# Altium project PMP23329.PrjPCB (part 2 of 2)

## Sheet MCU and Communication.SchDoc
size A3; Date: Not shown in title block; ApprovedBy: Not shown in title block; CheckedBy: Not shown in title block; Author: Not shown in title block; CompanyName: Not shown in title block; Engineer: Not shown in title block; Organization: Not shown in title block; Address1: Not shown in title block; Address2: Not shown in title block; Address3: Not shown in title block; Address4: Not shown in title block; DocumentNumber: 1; Revision: Use project parameter SCH_Rev; SheetNumber: 4; SheetTotal: 7; PageSetup: Record=PageOptions¦CenterHorizontal=True¦CenterVertical=True¦PrintScale=1.00¦XCorrection=1.00¦YCorrection=1.00¦PrintKind=0¦BorderSize=5000000¦LeftOffset=0¦BottomOffset=0¦Orientation=2¦PaperLength=1000¦PaperWidth=1000¦Scale=100¦PaperSource=15¦PrintQuality=600¦MediaType=1¦DitherType=10¦PaperKind=Letter¦PrintScaleMode=1
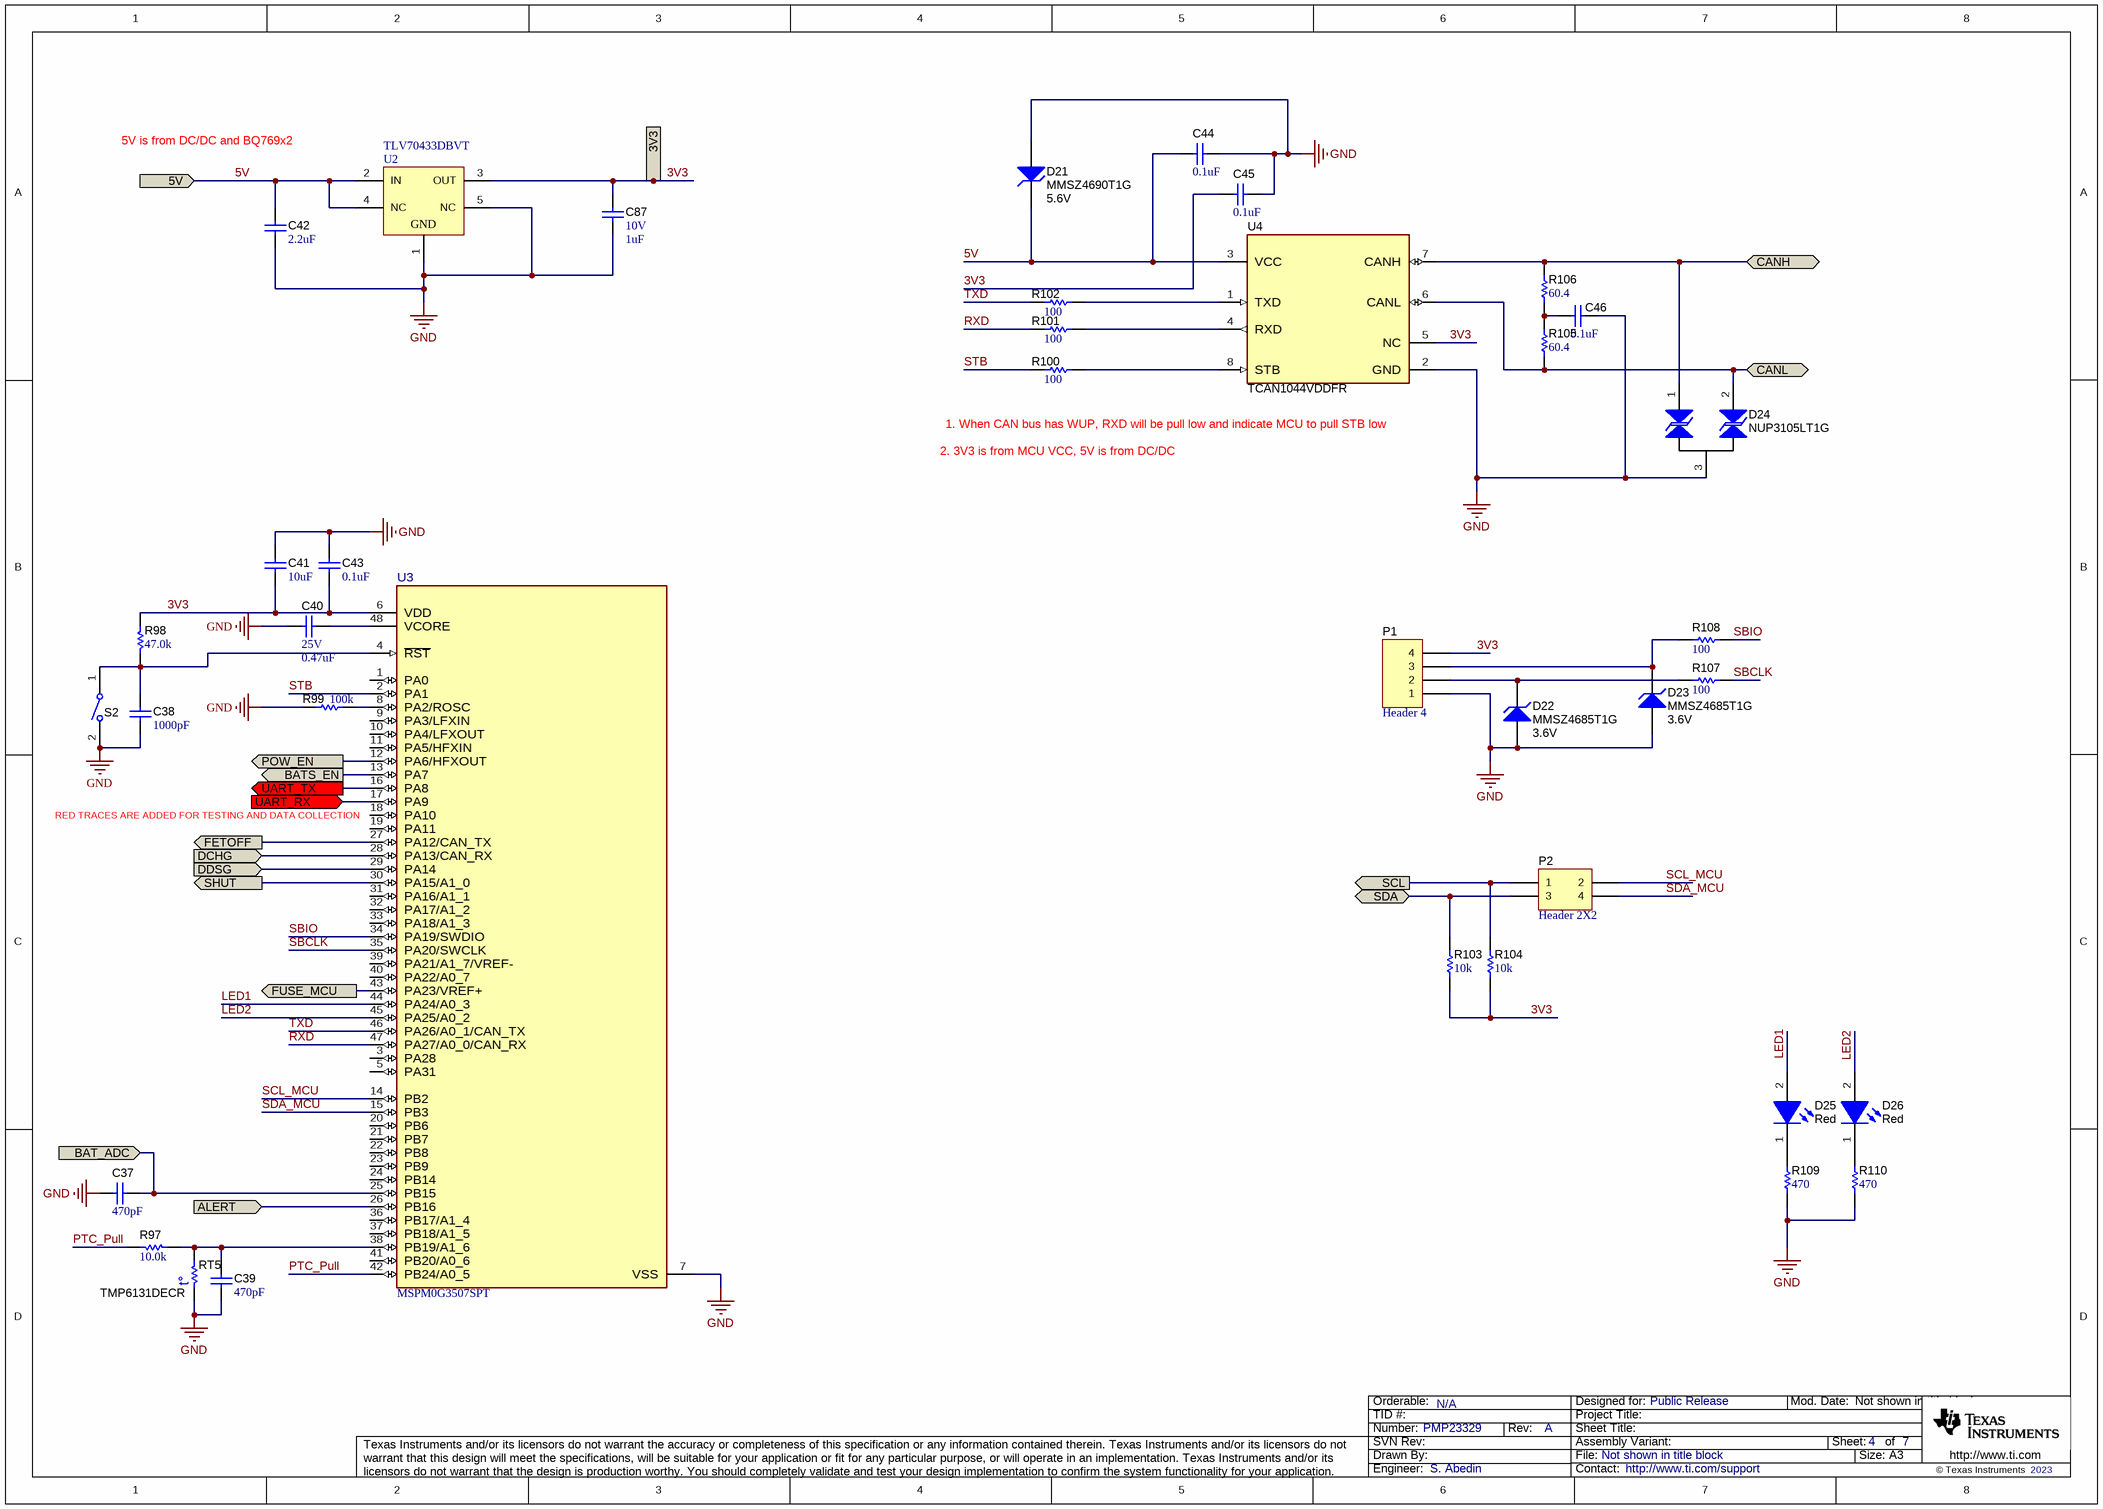
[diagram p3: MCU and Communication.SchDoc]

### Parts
C37  ValueDisplayed: 470pF  [0603S]  (hidden comment: GRM188R71H471KA01D)
C38  ValueDisplayed: 1000pF  [0603S]  (hidden comment: GRM1885C1H102JA01D)
C39  ValueDisplayed: 470pF  [0603S]  (hidden comment: GRM188R71H471KA01D)
C40  VDC_V: 25V  ValueDisplayed: 0.47uF  [1206L]  (hidden comment: 12063C474KAT2A)
C41  ValueDisplayed: 10uF  [0805_HV]  (hidden comment: CL21B106KOQNNNE)
C42  ValueDisplayed: 2.2uF  [0603S]  (hidden comment: EMK107BB7225MA-T)
C43  ValueDisplayed: 0.1uF  [0603S]  (hidden comment: GRM188R71H104KA93D)
C44  ValueDisplayed: 0.1uF  [0603S]  (hidden comment: GRM188R71H104KA93D)
C45  ValueDisplayed: 0.1uF  [0603S]  (hidden comment: GRM188R71H104KA93D)
C46  ValueDisplayed: 0.1uF  [0603S]  (hidden comment: GRM188R71H104KA93D)
C87  VDC_V: 10V  ValueDisplayed: 1uF  [0402S]  (hidden comment: GRM155R61A105KE15D)
D21  MMSZ4690T1G  value 5.6V  [SOD-123]
D22  MMSZ4685T1G  value 3.6V  [SOD-123]
D23  MMSZ4685T1G  value 3.6V  [SOD-123]
D24  NUP3105LT1G  [SOT-23]
D25  value Red  [WL-SMCW_RED]  (hidden comment: 150060RS75000)
D26  value Red  [WL-SMCW_RED]  (hidden comment: 150060RS75000)
P1  Header 4  [HDR1X4]
P2  Header 2X2  [HDR2X2]
R97  ValueDisplayed: 10.0k  [0603S]  (hidden comment: CRCW060310K0FKEA)
R98  ValueDisplayed: 47.0k  [0603S]  (hidden comment: RC0603FR-0747KL)
R99  ValueDisplayed: 100k  [0603S]  (hidden comment: RT0603BRD07100KL)
R100  ValueDisplayed: 100  [0603S]  (hidden comment: CRCW0603100RFKEA)
R101  ValueDisplayed: 100  [0603S]  (hidden comment: CRCW0603100RFKEA)
R102  ValueDisplayed: 100  [0603S]  (hidden comment: CRCW0603100RFKEA)
R103  ValueDisplayed: 10k  [0603S]  (hidden comment: CRCW060310K0JNEA)
R104  ValueDisplayed: 10k  [0603S]  (hidden comment: CRCW060310K0JNEA)
R105  ValueDisplayed: 60.4  [0603S]  (hidden comment: RC0603FR-0760R4L)
R106  ValueDisplayed: 60.4  [0603S]  (hidden comment: RC0603FR-0760R4L)
R107  ValueDisplayed: 100  [0603S]  (hidden comment: CRCW0603100RFKEA)
R108  ValueDisplayed: 100  [0603S]  (hidden comment: CRCW0603100RFKEA)
R109  ValueDisplayed: 470  [0603S]  (hidden comment: RC0603FR-07470RL)
R110  ValueDisplayed: 470  [0603S]  (hidden comment: RC0603FR-07470RL)
RT5  TMP6131DECR  [DEC0002A]
S2  RS-032G05A3-SM RT  [SW_RS-032G05A3-SM]  (value not drawn)
U2  TLV70433DBVT  [DBV0005A_N]
U3  MSPM0G3507SPT  [PT0048A-MFG]
U4  PartNumber: TCAN1044VDDFR  [DDF0008A-MFG]  (hidden comment: TCAN1044DDFRQ1)

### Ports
3V3 (out), 5V (in), ALERT (in), BAT_ADC (in), BATS_EN (out), CANH (bidir), CANL (bidir), DCHG (in), DDSG (in), FETOFF (out), FUSE_MCU (out), POW_EN (out), SCL (out), SDA (bidir), SHUT (out), UART_RX (in), UART_TX (out)

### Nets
GND: C37.1 C38.2 C39.2 C40.2 C41.1 C42.2 C43.1 C44.2 C45.2 C46.1 C87.2 D21.2(A) D22.2(A) D23.2(A) D24.3 P1.1 R99.1 R109.1 R110.1 RT5.1 S2.2 U2.1(GND) U2.5(NC) U3.7(VSS) U4.2(GND)
3V3: C41.2 C43.2 C45.1 C87.1 P1.4 R98.2 R103.1 R104.1 U2.3(OUT) U3.6(VDD) U4.5(NC) ; port 3V3
5V: C42.1 C44.1 D21.1(K) U2.2(IN) U2.4(NC) U4.3(VCC) ; port 5V
ALERT: U3.26(PB16) ; port ALERT
BAT_ADC: C37.2 U3.25(PB15) ; port BAT_ADC
BATS_EN: U3.13(PA7) ; port BATS_EN
CANH: D24.1 R106.1 U4.7(CANH) ; port CANH
CANL: D24.2 R105.2 U4.6(CANL) ; port CANL
DCHG: U3.28(PA13/CAN_RX) ; port DCHG
DDSG: U3.29(PA14) ; port DDSG
FETOFF: U3.27(PA12/CAN_TX) ; port FETOFF
FUSE_MCU: U3.43(PA23/VREF+) ; port FUSE_MCU
LED1: D25.2(A) U3.44(PA24/A0_3)
LED2: D26.2(A) U3.45(PA25/A0_2)
POW_EN: U3.12(PA6/HFXOUT) ; port POW_EN
PTC_Pull: R97.2 U3.42(PB24/A0_5)
RXD: R101.2 U3.47(PA27/A0_0/CAN_RX)
SBCLK: R107.1 U3.35(PA20/SWCLK)
SBIO: R108.1 U3.34(PA19/SWDIO)
SCL_MCU: P2.1 R104.2 ; port SCL
SCL_MCU: P2.2 U3.14(PB2)  [a separate net that carries the same name]
SDA_MCU: P2.3 R103.2 ; port SDA
SDA_MCU: P2.4 U3.15(PB3)  [a separate net that carries the same name]
SHUT: U3.30(PA15/A1_0) ; port SHUT
STB: R100.2 U3.2(PA1)
TXD: R102.2 U3.46(PA26/A0_1/CAN_TX)
UART_RX: U3.17(PA9) ; port UART_RX
UART_TX: U3.16(PA8) ; port UART_TX
NetC38_1: C38.1 R98.1 S2.1 U3.4(~{RST})
NetC39_1: C39.1 R97.1 RT5.2 U3.38(PB19/A1_6)
NetC40_1: C40.1 U3.48(VCORE)
NetC46_2: C46.2 R105.1 R106.2
NetD22_1: D22.1(K) P1.2 R107.2
NetD23_1: D23.1(K) P1.3 R108.2
NetD25_1: D25.1(K) R109.2
NetD26_1: D26.1(K) R110.2
NetR99_2: R99.2 U3.8(PA2/ROSC)
NetR100_1: R100.1 U4.8(STB)
NetR101_1: R101.1 U4.4(RXD)
NetR102_1: R102.1 U4.1(TXD)

Not connected (* = marked no-connect by the designer): U3 1(PA0) 3(PA28) 5(PA31) 9(PA3/LFXIN) 10(PA4/LFXOUT) 11(PA5/HFXIN) 18(PA10) 19(PA11) 20(PB6) 21(PB7) 22(PB8) 23(PB9) 24(PB14) 31(PA16/A1_1) 32(PA17/A1_2) 33(PA18/A1_3) 36(PB17/A1_4) 37(PB18/A1_5) 39(PA21/A1_7/VREF-) 40(PA22/A0_7) 41(PB20/A0_6)

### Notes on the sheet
- 5V is from DC/DC and BQ769x2
- 2. 3V3 is from MCU VCC, 5V is from DC/DC
- 1. When CAN bus has WUP, RXD will be pull low and indicate MCU to pull STB low
- RED TRACES ARE ADDED FOR TESTING AND DATA COLLECTION
- N/A

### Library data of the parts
C37 C39 = CMP-0007455-4: CAP, CERM, 470 pF, 50 V, +/- 10%, X7R, 0603; Manufacturer: MuRata; Polarized: N; Value: 470pF; U/M: EA; Value1: Unknown; VDC_V: 50V; TaMin_C: -55°C; TaMax_C: 125°C; Cap_Case: 0603; SizeArea_mm2: 1.28; SizeAreaWB_mm2: 4.68; SizeX_mm: 1.6; SizeY_mm: 0.8; SizeZ_mm: 1; AEC Category: Q200
C38 = CMP-0007173-4: CAP, CERM, 1000 pF, 50 V, +/- 5%, C0G/NP0, 0603; Manufacturer: MuRata; Polarized: N; Value: 1000pF; U/M: EA; Cap_F: 1nF; Value1: Unknown; VDC_V: 50V; TaMin_C: -55°C; TaMax_C: 125°C; Cap_Case: 0603; SizeArea_mm2: 1.28; SizeAreaWB_mm2: 4.68; SizeX_mm: 1.6; SizeY_mm: 0.8; SizeZ_mm: 1; AEC Category: Q200
C40 = CMP-0008510-2: CAP, CERM, 0.47 uF, 25 V, +/- 10%, X7R, 1206; Manufacturer: AVX; TaMin_C: -55°C; ESR_ohm: 18m; Polarized: N; SizeAreaWB_mm2: 10.92; Value1: 0.018 ohm; U/M: EA; Value: 0.47uF; TaMax_C: 125°C; SizeZ_mm: 1.35; SizeX_mm: 3.2; SizeY_mm: 1.6; Cap_Case: 1206; SizeArea_mm2: 5.12; Cap_F: 470nF; AEC Category: Q200
C41 = CMP-0007995-2: CAP, CERM, 10 uF, 16 V, +/- 10%, X7R, 0805; Manufacturer: Samsung Electro-Mechanics; Polarized: N; Value: 10uF; U/M: EA; Cap_F: 10µF; Value1: Unknown; VDC_V: 16V; TaMin_C: -55°C; TaMax_C: 125°C; Cap_Case: 0805; SizeArea_mm2: 2.5; SizeAreaWB_mm2: 6.75; SizeX_mm: 2; SizeY_mm: 1.25; SizeZ_mm: 1.45; AEC Category: Q200
C42 = CMP-0064934-4: CAP, CERM, 2.2 uF, 16 V,+/- 10%, X7R, 0603; Manufacturer: Taiyo Yuden; Polarized: N; Value: 2.2uF; U/M: EA; Cap_F: 2.2µF; Value1: Unknown; VDC_V: 16V; TaMin_C: -55°C; TaMax_C: 125°C; Cap_Case: 0603; SizeArea_mm2: 1.28; SizeAreaWB_mm2: 4.68; SizeX_mm: 1.6; SizeY_mm: 0.8; SizeZ_mm: 1; AEC Category: Q200
C43-C46 = CMP-0007434-4: CAP, CERM, 0.1 uF, 50 V, +/- 10%, X7R, 0603; Manufacturer: MuRata; Polarized: N; Value: 0.1uF; U/M: EA; Cap_F: 100nF; Value1: Unknown; VDC_V: 50V; TaMin_C: -55°C; TaMax_C: 125°C; Cap_Case: 0603; SizeArea_mm2: 1.28; SizeAreaWB_mm2: 4.68; SizeX_mm: 1.6; SizeY_mm: 0.8; SizeZ_mm: 1; AEC Category: Q200
C87 = CMP-0006563-2: CAP, CERM, 1 uF, 10 V, +/- 10%, X5R, 0402; Manufacturer: MuRata; TaMin_C: -55°C; Polarized: N; SizeAreaWB_mm2: 3; Value1: Unknown; U/M: EA; Value: 1uF; TaMax_C: 85°C; SizeZ_mm: 0.6; SizeX_mm: 1; SizeY_mm: 0.5; Cap_Case: 0402; Cap_F: 1µF; AEC Category: Q200
D21 = CMP-0005787-3: Diode, Zener, 5.6 V, 500 mW, SOD-123; Manufacturer: ON Semiconductor; Power_W: 500mW; Value1: 0.5W; RJA_CperW: 340; SizeAreaWB_mm2: 13.095; SizeArea_mm2: 6.545; SizeX_mm: 3.85; SizeY_mm: 1.7; SizeZ_mm: 1.35; AEC Category: Q101
D22 D23 = CMP-0005782-3: Diode, Zener, 3.6 V, 500 mW, SOD-123; Manufacturer: ON Semiconductor; Power_W: 500mW; Value1: 0.5W; RJA_CperW: 340; SizeAreaWB_mm2: 13.095; SizeArea_mm2: 6.545; SizeX_mm: 3.85; SizeY_mm: 1.7; SizeZ_mm: 1.35; AEC Category: Q101
D24 = CMP-0078391-3: Diode, TVS, Bi, 32 V, 66 Vc, AEC-Q101, SOT-23; Manufacturer: ON Semiconductor; Value: 32V; Value1: 350W; SizeAreaWB_mm2: 14; SizeArea_mm2: 7.5; SizeX_mm: 2.5; SizeY_mm: 3; SizeZ_mm: 1.1; AEC Category: Q101; AEC Qualified: Y; Ipp: 8A; Vbr_Min: 35.6V; Vc: 66V
D25 D26 = CMP-0002947-3: LED, Red, SMD; Manufacturer: Wurth Elektronik; Type: AlInGaP; Vf_V: 2V; Io_A: 30mA; Vr_V: 5V; Tjmax_C: 85°C; Power_TotalModule: 72mW; Value1: 0.072W; Angle: 140
P1 = Header 4: Header, 4-Pin
P2 = Header 2X2: Header, 2-Pin, Dual row
R97 = CMP-0021998-4: RES, 10.0 k, 1%, 0.1 W, AEC-Q200 Grade 0, 0603; Manufacturer: Vishay-Dale; Value: 10.0k; Res_ohm: 10k; Value_Code: 10k0; Power_W: 100mW; Value2: 0.1W; VDC_V: 75V; TempCo: 100 ppm/C; SizeArea_mm2: 1.28; SizeX_mm: 1.6; SizeY_mm: 0.8; SizeZ_mm: 1; EIA_Code: E96; AEC Category: Q200; AEC Qualified: Y; AEC Grade: 0
R98 = CMP-0023133-5: RES, 47.0 k, 1%, 0.1 W, 0603; Manufacturer: Yageo; Value: 47.0k; Res_ohm: 47k; Value_Code: 47k0; Power_W: 100mW; Value2: 0.1W; VDC_V: 75V; TempCo: 100 ppm/C; SizeArea_mm2: 1.28; SizeX_mm: 1.6; SizeY_mm: 0.8; SizeZ_mm: 1; AEC Category: Q200; AEC Qualified: N; SizeAreaWB_mm2: 4.68
R99 = CMP-0023630-3: RES, 100 k, 0.1%, 0.1 W, 0603; Manufacturer: Yageo America; Value: 100k; Power_W: 100mW; Value2: 0.1W; VDC_V: 75V; TempCo: 25 ppm/C; SizeArea_mm2: 1.28; SizeX_mm: 1.6; SizeY_mm: 0.8; SizeZ_mm: 1; EIA_Code: E192; U/M: EA; AEC Category: Q200
R100-R102 R107 R108 = CMP-0021991-4: RES, 100, 1%, 0.1 W, AEC-Q200 Grade 0, 0603; Manufacturer: Vishay-Dale; Value: 100; Value_Code: 100R; Power_W: 100mW; Value2: 0.1W; VDC_V: 75V; TempCo: 100 ppm/C; SizeArea_mm2: 1.28; SizeX_mm: 1.6; SizeY_mm: 0.8; SizeZ_mm: 1; EIA_Code: E96; AEC Category: Q200; AEC Qualified: Y; AEC Grade: 0
R103 R104 = CMP-0025701-4: RES, 10 k, 5%, 0.1 W, AEC-Q200 Grade 0, 0603; Manufacturer: Vishay-Dale; Value: 10k; Value_Code: 10k0; Power_W: 100mW; Value2: 0.1W; VDC_V: 75V; TempCo: 200 ppm/C; SizeArea_mm2: 1.28; SizeX_mm: 1.6; SizeY_mm: 0.8; SizeZ_mm: 1; EIA_Code: E24; AEC Category: Q200; AEC Qualified: Y; AEC Grade: 0
R105 R106 = CMP-0023213-5: RES, 60.4, 1%, 0.1 W, 0603; Manufacturer: Yageo; Value: 60.4; Value_Code: 60R4; Power_W: 100mW; Value2: 0.1W; VDC_V: 75V; TempCo: 100 ppm/C; SizeArea_mm2: 1.28; SizeX_mm: 1.6; SizeY_mm: 0.8; SizeZ_mm: 1; EIA_Code: E96; AEC Category: Q200; AEC Qualified: N; SizeAreaWB_mm2: 4.68
R109 R110 = CMP-0023129-5: RES, 470, 1%, 0.1 W, 0603; Manufacturer: Yageo; Value: 470; Value_Code: 470R; Power_W: 100mW; Value2: 0.1W; VDC_V: 75V; TempCo: 100 ppm/C; SizeArea_mm2: 1.28; SizeX_mm: 1.6; SizeY_mm: 0.8; SizeZ_mm: 1; AEC Category: Q200; AEC Qualified: N; SizeAreaWB_mm2: 4.68
RT5 = CMP-0084566-1: Thermistor, DEC0002A (X1SON-2); Alternate Manufacturer: Texas Instruments; Alternate PartNumber: TMP6131DECT; CompType: IC; AEC Category: Q200; SizeX_mm: 1; AEC Qualified: N; SizeZ_mm: 0.5; SizeArea_mm2: 0.6; SizeAreaWB_mm2: 3.2
S2 = CMP-0002210-1: Switch, Tactile, SPST-NO, 0.05A, 12V, SMD; Manufacturer: C&K Components; SwitchFunction: Off-Mom; PositionCount: 1; CurrentRating_mA: 50A
U2 = CMP-0035592-1: Single Output LDO, 150 mA, Fixed 3.3 V Output, 2.5 to 24 V Input, with Ultra-Low IQ, 5-pin SOT-23 (DBV), -40 to 125 degC, Green (RoHS & no Sb/Br); Manufacturer: Texas Instruments; Accuracy(%): 2; Fixed Output Options(V): 3.3; Iout(Max)(A): 0.15; Iq(Typ)(mA): 0.003; SubFamily: Single Channel LDO; Vdo(Typ)(mV): 400; Vin(Max)(V): 24; Vin(Min)(V): 2.5
U3 = CMP-0093961-1: Mixed-Signal Microcontrollers with CAN-FD Interface ARM Cortex-M0+ 32bits 128KB Flash 32KB RAM LQFP48 AEC Q-200 Grade 1 80MHz; Manufacturer: Texas Instruments; Number Of I/Os: 44; Interface: I2C,SPI,UART,CAN,LIN,IrDA,SMBus; Number Of I2C Channels: 2; AEC Grade: Grade 1; TaMin_C: -40°C; Number Of Adc Channels: 15; Standoff Height: 0.05mm; Ram Size: 32KBytes; Number Of Pwm Channels: 20; Min Supply Voltage: 1.62V; AEC Qualified: Yes; Number Of Timers/Counters: 6; SizeZ_mm: 1.6mm; Number Of Cores: 1; TaMax_C: +125°C; TJmax_C: +130°C; Memory Size: 128KBytes; Max Supply Voltage: 3.6V; Number Of Uart Channels: 4
U4 = CMP-0089901-1: Automotive High Speed CAN Transceiver; Manufacturer: Texas Instruments; Min Supply Voltage: 4.5V; TaMin_C: -40°C; AEC Grade: Grade 1; Standoff Height: 0mm; SizeZ_mm: 1.1mm; TaMax_C: +125°C; Max Supply Voltage: 5.5V; Nominal Supply Current: 5-180mA; TJmax_C: +150°C; AEC Qualified: Yes

## Sheet High-side MOSFETs and driver.SchDoc
size A3; Date: Not shown in title block; ApprovedBy: Not shown in title block; CheckedBy: Not shown in title block; Author: Not shown in title block; CompanyName: Not shown in title block; Engineer: Not shown in title block; Organization: Not shown in title block; Address1: Not shown in title block; Address2: Not shown in title block; Address3: Not shown in title block; Address4: Not shown in title block; DocumentNumber: 1; Revision: Use project parameter SCH_Rev; SheetNumber: 6; SheetTotal: 7; PageSetup: Record=PageOptions¦CenterHorizontal=True¦CenterVertical=True¦PrintScale=1.00¦XCorrection=1.00¦YCorrection=1.00¦PrintKind=0¦BorderSize=5000000¦LeftOffset=0¦BottomOffset=0¦Orientation=2¦PaperLength=1000¦PaperWidth=1000¦Scale=100¦PaperSource=15¦PrintQuality=600¦MediaType=1¦DitherType=10¦PaperKind=Letter¦PrintScaleMode=1
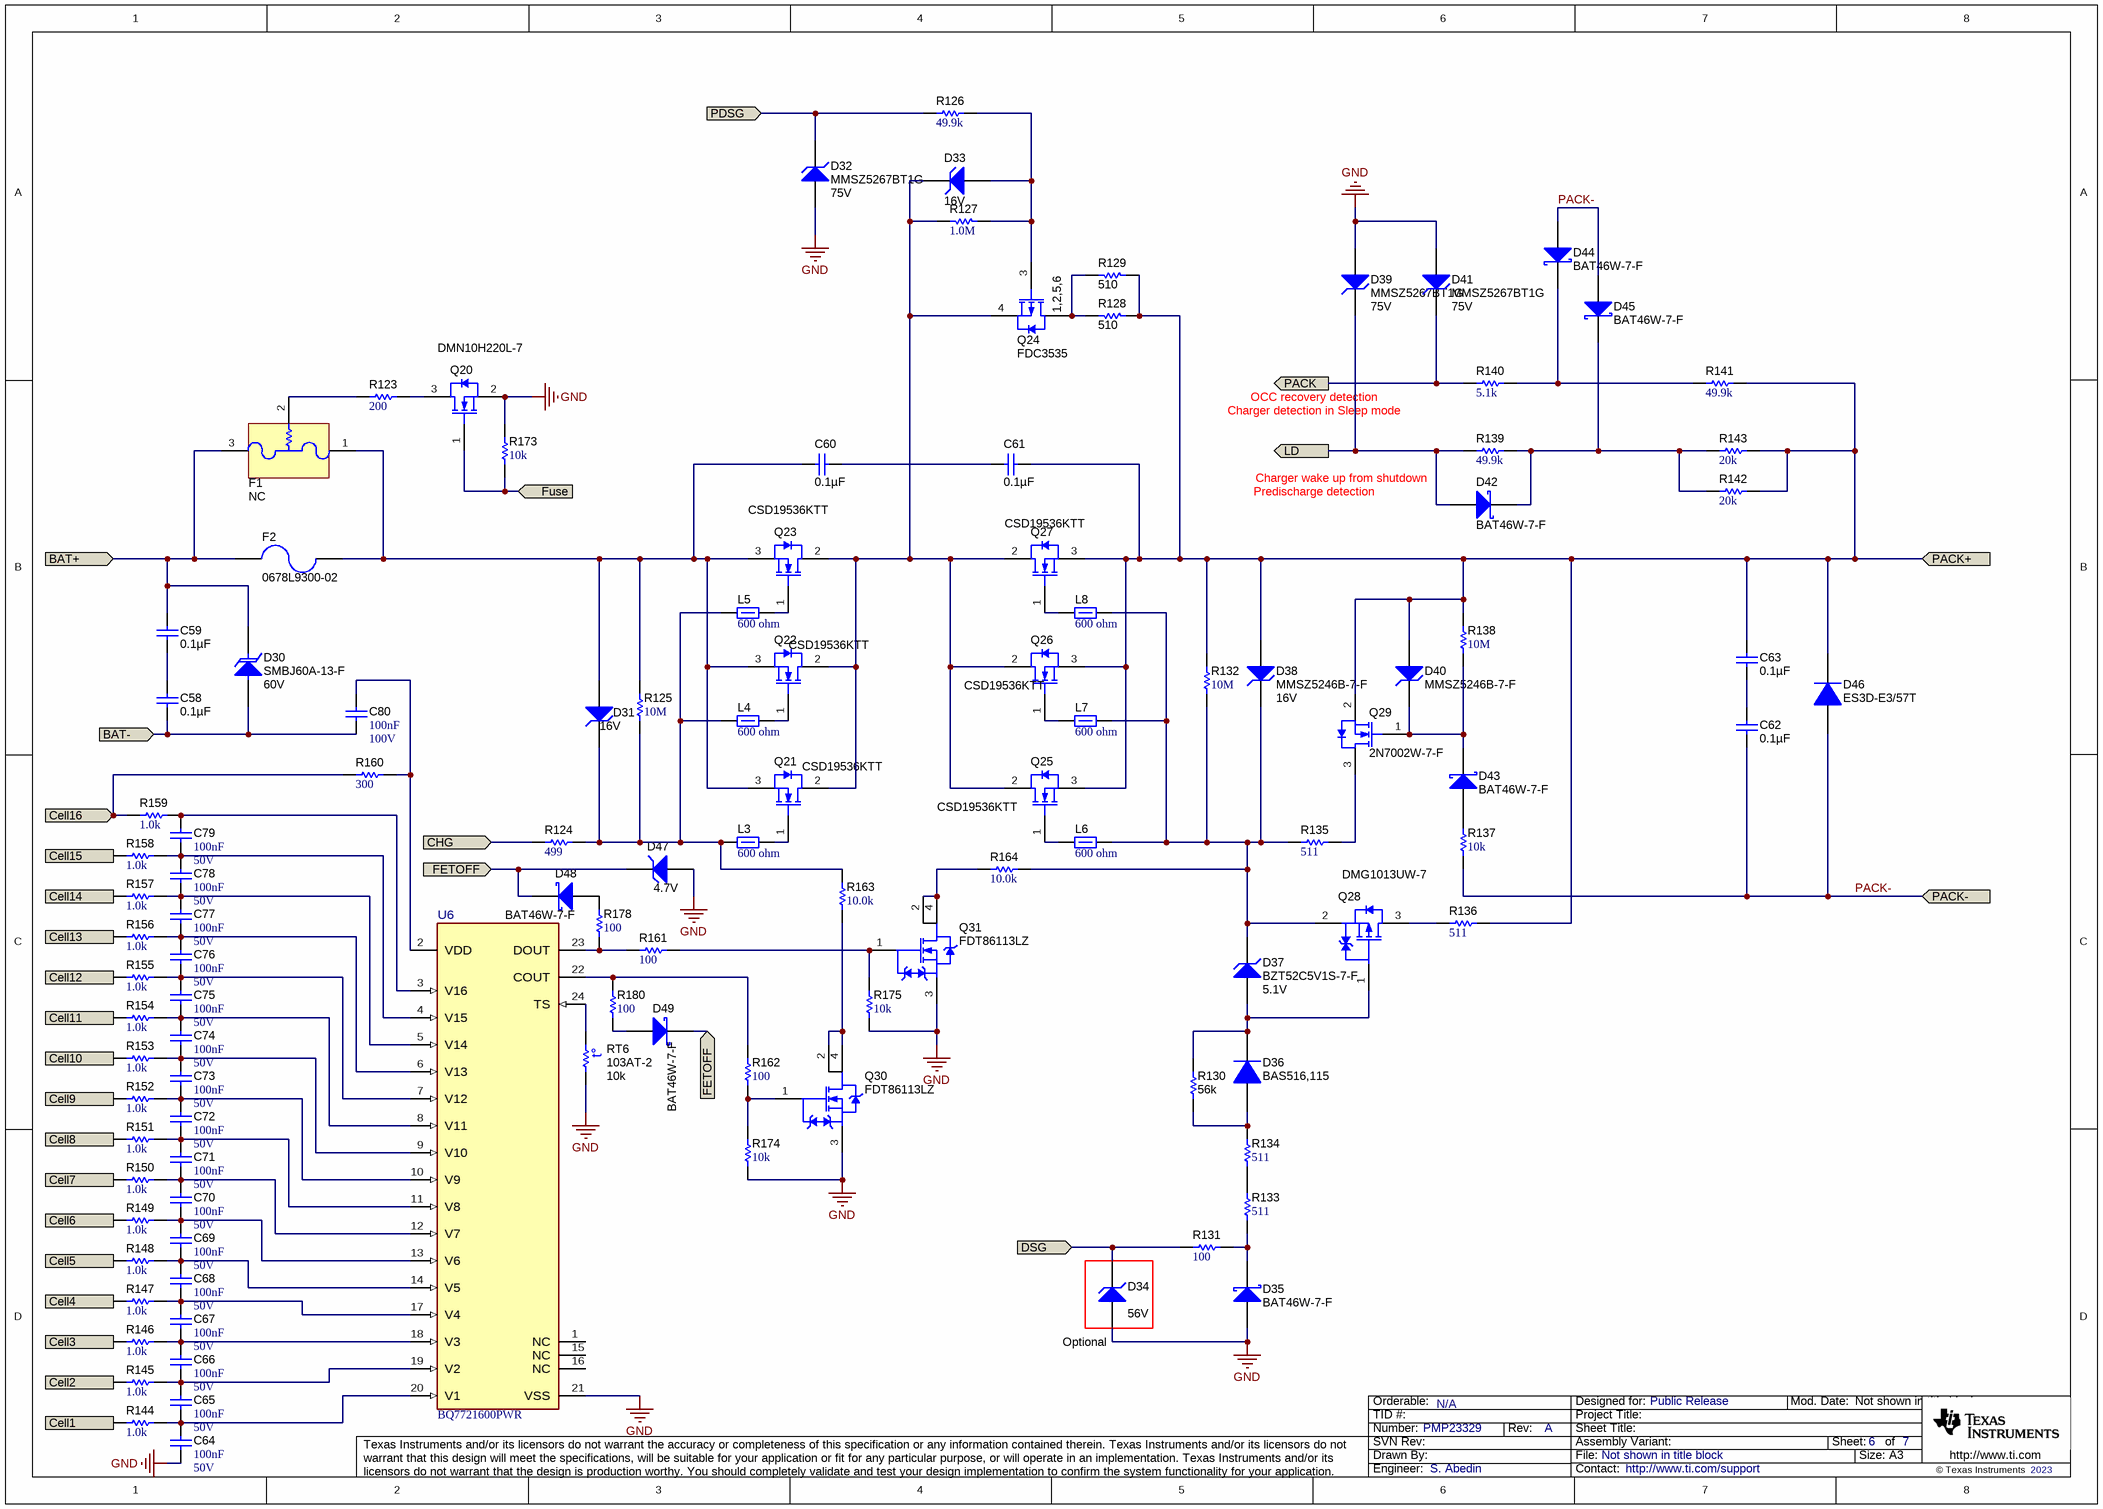
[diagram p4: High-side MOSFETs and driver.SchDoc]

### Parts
C58  ValueDisplayed: 0.1µF  [0603S]  (hidden comment: GRM188R72A104KA35D)
C59  ValueDisplayed: 0.1µF  [0603S]  (hidden comment: GRM188R72A104KA35D)
C60  ValueDisplayed: 0.1µF  [0603S]  (hidden comment: GRM188R72A104KA35D)
C61  ValueDisplayed: 0.1µF  [0603S]  (hidden comment: GRM188R72A104KA35D)
C62  ValueDisplayed: 0.1µF  [0603S]  (hidden comment: GRM188R72A104KA35D)
C63  ValueDisplayed: 0.1µF  [0603S]  (hidden comment: GRM188R72A104KA35D)
C64  Cap_F: 100nF  VDC_V: 50V  [0603S]  (hidden comment: 885012206095)
C65  Cap_F: 100nF  VDC_V: 50V  [0603S]  (hidden comment: 885012206095)
C66  Cap_F: 100nF  VDC_V: 50V  [0603S]  (hidden comment: 885012206095)
C67  Cap_F: 100nF  VDC_V: 50V  [0603S]  (hidden comment: 885012206095)
C68  Cap_F: 100nF  VDC_V: 50V  [0603S]  (hidden comment: 885012206095)
C69  Cap_F: 100nF  VDC_V: 50V  [0603S]  (hidden comment: 885012206095)
C70  Cap_F: 100nF  VDC_V: 50V  [0603S]  (hidden comment: 885012206095)
C71  Cap_F: 100nF  VDC_V: 50V  [0603S]  (hidden comment: 885012206095)
C72  Cap_F: 100nF  VDC_V: 50V  [0603S]  (hidden comment: 885012206095)
C73  Cap_F: 100nF  VDC_V: 50V  [0603S]  (hidden comment: 885012206095)
C74  Cap_F: 100nF  VDC_V: 50V  [0603S]  (hidden comment: 885012206095)
C75  Cap_F: 100nF  VDC_V: 50V  [0603S]  (hidden comment: 885012206095)
C76  Cap_F: 100nF  VDC_V: 50V  [0603S]  (hidden comment: 885012206095)
C77  Cap_F: 100nF  VDC_V: 50V  [0603S]  (hidden comment: 885012206095)
C78  Cap_F: 100nF  VDC_V: 50V  [0603S]  (hidden comment: 885012206095)
C79  Cap_F: 100nF  VDC_V: 50V  [0603S]  (hidden comment: 885012206095)
C80  Cap_F: 100nF  VDC_V: 100V  [0603S]  (hidden comment: GCJ188R72A104KA01D)
D30  SMBJ60A-13-F  value 60V  [SMB]
D31  value 16V  [SOD-123]  (hidden comment: MMSZ5246B-7-F)
D32  MMSZ5267BT1G  value 75V  [SOD-123]
D33  value 16V  [SOD-123]  (hidden comment: MMSZ5246B-7-F)
D34  value 56V  [SOD-123]  (hidden comment: MMSZ5263BT1G)
D35  BAT46W-7-F  [SOD-123]
D36  BAS516,115  [SOD-523]
D37  BZT52C5V1S-7-F  value 5.1V  [SOD-323]
D38  MMSZ5246B-7-F  value 16V  [SOD-123]
D39  MMSZ5267BT1G  value 75V  [SOD-123]
D40  MMSZ5246B-7-F  [SOD-123]
D41  MMSZ5267BT1G  value 75V  [SOD-123]
D42  BAT46W-7-F  [SOD-123]
D43  BAT46W-7-F  [SOD-123]
D44  BAT46W-7-F  [SOD-123]
D45  BAT46W-7-F  [SOD-123]
D46  ES3D-E3/57T  [SMC]
D47  value 4.7V  [SOD-323]  (hidden comment: CMDZ4L7 TR)
D48  BAT46W-7-F  [SOD-123]
D49  BAT46W-7-F  [SOD-123]
F1  NC  [FUSE_SFK-xx30x]
F2  0678L9300-02  [Fuse_0678L]
L3  ValueDisplayed: 600 ohm  [0603S]  (hidden comment: 74279265)
L4  ValueDisplayed: 600 ohm  [0603S]  (hidden comment: 74279265)
L5  ValueDisplayed: 600 ohm  [0603S]  (hidden comment: 74279265)
L6  ValueDisplayed: 600 ohm  [0603S]  (hidden comment: 74279265)
L7  ValueDisplayed: 600 ohm  [0603S]  (hidden comment: 74279265)
L8  ValueDisplayed: 600 ohm  [0603S]  (hidden comment: 74279265)
Q20  DMN10H220L-7  [SOT-23]
Q21  CSD19536KTT  [KTT0002A]
Q22  CSD19536KTT  [KTT0002A]
Q23  CSD19536KTT  [KTT0002A]
Q24  FDC3535  [SSOT-6]
Q25  CSD19536KTT  [KTT0002A]
Q26  CSD19536KTT  [KTT0002A]
Q27  CSD19536KTT  [KTT0002A]
Q28  DMG1013UW-7  [SOT-323]
Q29  2N7002W-7-F  [SOT-323]
Q30  FDT86113LZ  [SOT-223]
Q31  FDT86113LZ  [SOT-223]
R123  ValueDisplayed: 200  [0603S]  (hidden comment: CRCW0603200RFKEA)
R124  ValueDisplayed: 499  [1206L]  (hidden comment: ERJ-8ENF4990V)
R125  ValueDisplayed: 10M  [0603S]  (hidden comment: CRCW060310M0JNEA)
R126  ValueDisplayed: 49.9k  [0603S]  (hidden comment: RT0603BRD0749K9L)
R127  ValueDisplayed: 1.0M  [0603S]  (hidden comment: CRCW06031M00JNEA)
R128  ValueDisplayed: 510  [2512]  (hidden comment: RC2512JK-07510RL)
R129  ValueDisplayed: 510  [2512]  (hidden comment: RC2512JK-07510RL)
R130  ValueDisplayed: 56k  [0805_HV]  (hidden comment: RC0805JR-0756KL)
R131  ValueDisplayed: 100  [0603S]  (hidden comment: CRCW0603100RFKEA)
R132  ValueDisplayed: 10M  [0603S]  (hidden comment: CRCW060310M0JNEA)
R133  ValueDisplayed: 511  [0805_HV1]  (hidden comment: CRCW0805511RFKEA)
R134  ValueDisplayed: 511  [0805_HV]  (hidden comment: CRCW0805511RFKEA)
R135  ValueDisplayed: 511  [0805_HV]  (hidden comment: CRCW0805511RFKEA)
R136  ValueDisplayed: 511  [0603S]  (hidden comment: CRCW0603511RFKEA)
R137  ValueDisplayed: 10k  [0603S]  (hidden comment: CRCW060310K0JNEA)
R138  ValueDisplayed: 10M  [0603S]  (hidden comment: CRCW060310M0JNEA)
R139  ValueDisplayed: 49.9k  [0603S]  (hidden comment: RT0603BRD0749K9L)
R140  ValueDisplayed: 5.1k  [0603S]  (hidden comment: CRCW06035K10JNEA)
R141  ValueDisplayed: 49.9k  [0603S]  (hidden comment: RT0603BRD0749K9L)
R142  ValueDisplayed: 20k  [0603S]  (hidden comment: CRCW060320K0JNEA)
R143  ValueDisplayed: 20k  [0603S]  (hidden comment: CRCW060320K0JNEA)
R144  ValueDisplayed: 1.0k  [0402S]  (hidden comment: ERJ-2GEJ102X)
R145  ValueDisplayed: 1.0k  [0402S]  (hidden comment: ERJ-2GEJ102X)
R146  ValueDisplayed: 1.0k  [0402S]  (hidden comment: ERJ-2GEJ102X)
R147  ValueDisplayed: 1.0k  [0402S]  (hidden comment: ERJ-2GEJ102X)
R148  ValueDisplayed: 1.0k  [0402S]  (hidden comment: ERJ-2GEJ102X)
R149  ValueDisplayed: 1.0k  [0402S]  (hidden comment: ERJ-2GEJ102X)
R150  ValueDisplayed: 1.0k  [0402S]  (hidden comment: ERJ-2GEJ102X)
R151  ValueDisplayed: 1.0k  [0402S]  (hidden comment: ERJ-2GEJ102X)
R152  ValueDisplayed: 1.0k  [0402S]  (hidden comment: ERJ-2GEJ102X)
R153  ValueDisplayed: 1.0k  [0402S]  (hidden comment: ERJ-2GEJ102X)
R154  ValueDisplayed: 1.0k  [0402S]  (hidden comment: ERJ-2GEJ102X)
R155  ValueDisplayed: 1.0k  [0402S]  (hidden comment: ERJ-2GEJ102X)
R156  ValueDisplayed: 1.0k  [0402S]  (hidden comment: ERJ-2GEJ102X)
R157  ValueDisplayed: 1.0k  [0402S]  (hidden comment: ERJ-2GEJ102X)
R158  ValueDisplayed: 1.0k  [0402S]  (hidden comment: ERJ-2GEJ102X)
R159  ValueDisplayed: 1.0k  [0402S]  (hidden comment: ERJ-2GEJ102X)
R160  ValueDisplayed: 300  [0603S]  (hidden comment: CRCW0603300RJNEA)
R161  ValueDisplayed: 100  [0603S]  (hidden comment: CRCW0603100RJNEA)
R162  ValueDisplayed: 100  [0603S]  (hidden comment: CRCW0603100RJNEA)
R163  ValueDisplayed: 10.0k  [1206]  (hidden comment: CRCW120610K0FKEAHP)
R164  ValueDisplayed: 10.0k  [1206]  (hidden comment: CRCW120610K0FKEAHP)
R173  ValueDisplayed: 10k  [0603S]  (hidden comment: CRCW060310K0JNEA)
R174  ValueDisplayed: 10k  [0603S]  (hidden comment: CRCW060310K0JNEA)
R175  ValueDisplayed: 10k  [0603S]  (hidden comment: CRCW060310K0JNEA)
R178  ValueDisplayed: 100  [0603S]  (hidden comment: CRCW0603100RJNEA)
R180  ValueDisplayed: 100  [0603S]  (hidden comment: CRCW0603100RJNEA)
RT6  103AT-2  value 10k  [THERMISTOR_103AT-2]
U6  BQ7721600PWR  [PW0024A-MFG]

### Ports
BAT+ (in), BAT- (in), Cell1 (in), Cell2 (in), Cell3 (in), Cell4 (in), Cell5 (in), Cell6 (in), Cell7 (in), Cell8 (in), Cell9 (in), Cell10 (in), Cell11 (in), Cell12 (in), Cell13 (in), Cell14 (in), Cell15 (in), Cell16 (in), CHG (in), DSG (in), FETOFF (in), Fuse (in), LD (out), PACK (out), PACK+ (in), PACK- (in), PDSG (in)

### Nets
GND: C64.2 D32.2(A) D34.2(A) D35.2(A) D39.2(A) D41.2(A) D47.2(A) Q20.2(S) Q30.3(S) Q31.3(S) R173.2 R174.1 R175.1 RT6.1 U6.21(VSS)
BAT+: C59.1 D30.1(K) F1.3(Fuse) F2.2 ; port BAT+
BAT-: C58.2 C80.2 D30.2(A) ; port BAT-
Cell1: R144.1 ; port Cell1
Cell2: R145.1 ; port Cell2
Cell3: R146.1 ; port Cell3
Cell4: R147.1 ; port Cell4
Cell5: R148.1 ; port Cell5
Cell6: R149.1 ; port Cell6
Cell7: R150.1 ; port Cell7
Cell8: R151.1 ; port Cell8
Cell9: R152.1 ; port Cell9
Cell10: R153.1 ; port Cell10
Cell11: R154.1 ; port Cell11
Cell12: R155.1 ; port Cell12
Cell13: R156.1 ; port Cell13
Cell14: R157.1 ; port Cell14
Cell15: R158.1 ; port Cell15
Cell16: R159.1 R160.2 ; port Cell16
CHG: R124.1 ; port CHG
DSG: D34.1(K) R131.1 ; port DSG
FETOFF: D47.1(K) D48.1(K) D49.1(K) ; port FETOFF
Fuse: Q20.1(G) R173.1 ; port Fuse
LD: D39.1(K) D42.2(A) R139.1 ; port LD
PACK: D41.1(K) R140.1 ; port PACK
PACK+: C61.1 C63.1 D38.2(A) D40.2(A) D46.1(K) Q25.3(S) Q26.3(S) Q27.3(S) Q29.2(S) R128.1 R129.1 R132.2 R136.2 R138.1 R141.2 R142.2 R143.2 ; port PACK+
PACK-: C62.2 D44.2(A) D45.2(A) D46.2(A) R137.1 ; port PACK-
PDSG: D32.1(K) R126.1 ; port PDSG
NetC58_1: C58.1 C59.2
NetC60_1: C60.1 C61.2
NetC60_2: C60.2 D31.2(A) F1.1(Fuse) F2.1 Q21.3(S) Q22.3(S) Q23.3(S) R125.2
NetC62_1: C62.1 C63.2
NetC64_1: C64.1 C65.2 R144.2 U6.20(V1)
NetC65_1: C65.1 C66.2 R145.2 U6.19(V2)
NetC66_1: C66.1 C67.2 R146.2 U6.18(V3)
NetC67_1: C67.1 C68.2 R147.2 U6.17(V4)
NetC68_1: C68.1 C69.2 R148.2 U6.14(V5)
NetC69_1: C69.1 C70.2 R149.2 U6.13(V6)
NetC70_1: C70.1 C71.2 R150.2 U6.12(V7)
NetC71_1: C71.1 C72.2 R151.2 U6.11(V8)
NetC72_1: C72.1 C73.2 R152.2 U6.10(V9)
NetC73_1: C73.1 C74.2 R153.2 U6.9(V10)
NetC74_1: C74.1 C75.2 R154.2 U6.8(V11)
NetC75_1: C75.1 C76.2 R155.2 U6.7(V12)
NetC76_1: C76.1 C77.2 R156.2 U6.6(V13)
NetC77_1: C77.1 C78.2 R157.2 U6.5(V14)
NetC78_1: C78.1 C79.2 R158.2 U6.4(V15)
NetC79_1: C79.1 R159.2 U6.3(V16)
NetC80_1: C80.1 R160.1 U6.2(VDD)
NetD31_1: D31.1(K) L3.1 L4.1 L5.1 R124.2 R125.1 R163.2
NetD33_1: D33.1(K) Q21.2(D) Q22.2(D) Q23.2(D) Q24.4(S) Q25.2(D) Q26.2(D) Q27.2(D) R127.2
NetD33_2: D33.2(A) Q24.3(G) R126.2 R127.1
NetD35_1: D35.1(K) R131.2 R133.1
NetD36_1: D36.1(K) D37.2(A) Q28.1(G) R130.2
NetD36_2: D36.2(A) R130.1 R134.1
NetD37_1: D37.1(K) D38.1(K) L6.1 L7.1 L8.1 Q28.2(S) R132.1 R135.1 R164.1
NetD40_1: D40.1(K) D43.1(K) Q29.1(G) R138.2
NetD42_1: D42.1(K) D45.1(K) R139.2 R142.1 R143.1
NetD43_2: D43.2(A) R137.2
NetD44_1: D44.1(K) R140.2 R141.1
NetD48_2: D48.2(A) R178.1
NetD49_2: D49.2(A) R180.1
NetF1_2: F1.2(Heater) R123.1
NetL3_2: L3.2 Q21.1(G)
NetL4_2: L4.2 Q22.1(G)
NetL5_2: L5.2 Q23.1(G)
NetL6_2: L6.2 Q25.1(G)
NetL7_2: L7.2 Q26.1(G)
NetL8_2: L8.2 Q27.1(G)
NetQ20_3: Q20.3(D) R123.2
NetQ24_1: Q24.1(D) Q24.2(D) Q24.5(D) Q24.6(D) R128.2 R129.2
NetQ28_3: Q28.3(D) R136.1
NetQ29_3: Q29.3(D) R135.2
NetQ30_1: Q30.1(G) R162.1 R174.2
NetQ30_2: Q30.2(D) Q30.4(D) R163.1
NetQ31_1: Q31.1(G) R161.1 R175.2
NetQ31_2: Q31.2(D) Q31.4(D) R164.2
NetR133_2: R133.2 R134.2
NetR161_2: R161.2 R178.2 U6.23(DOUT)
NetR162_2: R162.2 R180.2 U6.22(COUT)
NetRT6_2: RT6.2 U6.24(TS)

Not connected (* = marked no-connect by the designer): U6 1(NC) 15(NC) 16(NC)

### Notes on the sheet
- OCC recovery detection
- Charger detection in Sleep mode
- Predischarge detection
- Charger wake up from shutdown
- (near D34) Optional
- N/A

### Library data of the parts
C58-C63 = GRM188R72A104KA35D: CAP, CERM, 0.1 µF, 100 V,+/- 10%, X7R, 0603; Manufacturer: MuRata; Polarized: N; CompType: Capacitor; Value: 0.1uF; U/M: EA; Cap_F: 0.0000001; Tolerance_%: 10; VDC_V: 100; Value2: 100V; TaMin_C: -55; TaMax_C: 125; Cap_Case: 0603; SizeArea_mm2: 1.28; SizeAreaWB_mm2: 4.68; SizeX_mm: 1.6; SizeY_mm: 0.8; SizeZ_mm: 1; AEC Category: Q200; Green_Lifecycle: Active; Green_REACh: Passed
C64-C79 = CMP-0006837-2: CAP, CERM, 0.1 uF, 50 V, +/- 10%, X7R, 0603; Manufacturer: Wurth Elektronik; TaMin_C: -55°C; Polarized: N; SizeAreaWB_mm2: 4.68; Value1: Unknown; U/M: EA; Value: 0.1uF; TaMax_C: 125°C; SizeZ_mm: 1; SizeX_mm: 1.6; SizeY_mm: 0.8; Cap_Case: 0603; SizeArea_mm2: 1.28; AEC Category: Q200
C80 = CMP-0064935-2: CAP, CERM, 0.1 uF, 100 V,+/- 10%, X7R, AEC-Q200 Grade 1, 0603; Manufacturer: MuRata; TaMin_C: -55°C; Polarized: N; SizeAreaWB_mm2: 4.68; Value1: Unknown; U/M: EA; Value: 0.1uF; TaMax_C: 125°C; SizeZ_mm: 1; SizeX_mm: 1.6; SizeY_mm: 0.8; Cap_Case: 0603; SizeArea_mm2: 1.28; AEC Qualified: Y; AEC Category: Q200
D30 = CMP-0005584-3: Diode, TVS, Uni, 60 V, 96.8 Vc, SMB; Manufacturer: Diodes Inc.; Value1: 600W; SizeAreaWB_mm2: 44.156; SizeArea_mm2: 21.336; SizeX_mm: 5.6; SizeY_mm: 3.81; SizeZ_mm: 2.6; AEC Category: Q101; Ipp: 6.2A; Vbr_Max: 76.7V; Vbr_Min: 66.7V; Vc: 96.8V
D31 D33 D38 = CMP-0005754-4: Diode, Zener, 16 V, 500 mW, SOD-123; Manufacturer: Diodes Inc.; Power_W: 500mW; Value1: 0.5W; RJA_CperW: 350; SizeAreaWB_mm2: 13.095; SizeArea_mm2: 6.545; SizeX_mm: 3.85; SizeY_mm: 1.7; SizeZ_mm: 1.35; AEC Category: Q101
D32 D39 D41 = MMSZ5263BT1G: Diode, Zener, 75V, 500 mW, AEC-Q101, SOD-123; Manufacturer: ON Semiconductor; SymbolCreator: a0412235; U/M: EA; Power_W: 0.5; Vz_V: 56; Value1: 0.5W; RJA_CperW: 340; SizeAreaWB_mm2: 13.095; SizeArea_mm2: 6.545; SizeX_mm: 3.85; SizeY_mm: 1.7; SizeZ_mm: 1.35; AEC Category: Q101; AEC Qualified: Y
D34 = CMP-0005738-4: Diode, Zener, 56 V, 500 mW, AEC-Q101, SOD-123; Manufacturer: ON Semiconductor; Power_W: 500mW; Value1: 0.5W; RJA_CperW: 340; SizeAreaWB_mm2: 13.095; SizeArea_mm2: 6.545; SizeX_mm: 3.85; SizeY_mm: 1.7; SizeZ_mm: 1.35; AEC Category: Q101; AEC Qualified: Y
D35 D42-D45 D48 D49 = CMP-0028450-2: Diode, Schottky, 100 V, 0.15 A, SOD-123; Manufacturer: Diodes Inc.; Vf_V: 600mV; Value: 100V; Value1: 0.15A; Value2: 0.6V; Io_A: 150mA; SizeAreaWB_mm2: 13.095; SizeArea_mm2: 6.545; SizeX_mm: 3.85; SizeY_mm: 1.7; SizeZ_mm: 1.35; AEC Category: Q101; Green_Lifecycle: Active; Green_REACh: Passed
D36 = CMP-0076979-3: Diode, Switching, 100 V, 0.25 A, SOD-523; Manufacturer: Nexperia; Vf_V: 1.25V; Value: 100V; Value1: 0.25A; Io_A: 250mA; TJmax_C: 150°C; SizeAreaWB_mm2: 5.13; SizeArea_mm2: 1.53; SizeX_mm: 1.7; SizeY_mm: 0.9; SizeZ_mm: 0.65; AEC Category: Q101; Green_Lifecycle: Not Set; Green_REACh: Incomplete
D37 = CMP-0005865-3: Diode, Zener, 5.1 V, 200 mW, SOD-323; Manufacturer: Diodes Inc.; Power_W: 200mW; Value1: 0.2W; RJA_CperW: 625; SizeAreaWB_mm2: 8.695; SizeArea_mm2: 3.645; SizeX_mm: 2.7; SizeY_mm: 1.35; SizeZ_mm: 1; AEC Category: Q101
D40 = CMP-0005754-4: Diode, Zener, 16 V, 500 mW, SOD-123; Manufacturer: Diodes Inc.; Value: 16V; Power_W: 500mW; Value1: 0.5W; RJA_CperW: 350; SizeAreaWB_mm2: 13.095; SizeArea_mm2: 6.545; SizeX_mm: 3.85; SizeY_mm: 1.7; SizeZ_mm: 1.35; AEC Category: Q101
D46 = CMP-0029041-2: Diode, Ultrafast, 200 V, 3 A, SMC; Manufacturer: Vishay-Semiconductor; Vf_V: 900mV; Value: 200V; Value1: 3A; Value2: 0.9V; TJmax_C: 150°C; SizeAreaWB_mm2: 83.2686; SizeArea_mm2: 50.5686; SizeX_mm: 8.13; SizeY_mm: 6.22; SizeZ_mm: 2.6; AEC Category: Q101; Green_Lifecycle: Not Set; Green_REACh: Incomplete
D47 = CMP-0005863-2: Diode, Zener, 4.7 V, 250 mW, SOD-323; Manufacturer: Central Semiconductor; SizeZ_mm: 1; SizeX_mm: 2.7; Value1: 0.25W; SizeAreaWB_mm2: 8.695; AEC Category: Q101; Power_W: 250mW; SizeY_mm: 1.35; RJA_CperW: 500; SizeArea_mm2: 3.645
F1 = SFK-5030: Manufacturer: POLYTRONICS; SymbolCreator: x0208325; CompType: Fuse; VDC_V: 62; Irating_A: 30; Rtyp_Ohm: 0.0015
F2 = 0678L9150-02: Fuse, 30 A, 250 VAC, 72 VDC, SMD; Manufacturer: Bel Fuse; SizeAreaWB_mm2: 59.59; SizeArea_mm2: 29.89; SizeX_mm: 9.8; SizeY_mm: 3.05; SizeZ_mm: 3.18; VDC_V: 72; VAC_V: 250; Irating_A: 15; Rtyp_Ohm: 0.0036; MeltingTyp: 110
L3-L8 = CMP-0003196-2: Ferrite Bead, 600 ohm @ 100 MHz, 0.2 A, 0603; Manufacturer: Wurth Elektronik; Value: 600 ohm; Imax_A: 200mA; DCR_ohm: 0.45; Value1: 0.45 ohm; Value2: 0.2A; SizeAreaWB_mm2: 4.68; SizeArea_mm2: 1.28; SizeX_mm: 1.6; SizeY_mm: 0.8; SizeZ_mm: 1; ZTyp@100MHz_Ohm: 600; Ztyp@1GHz_Ohm: 223.805
Q20 = CMP-0000971-2: MOSFET, N-CH, 100 V, 1.4 A, SOT-23; Manufacturer: Diodes Inc.; Alternate Manufacturer: None; U/M: EA; ChType: N; Value: 100V; Value1: 0.2; Rdson45_ohm: 0.25; Value2: 4.1 nC; QgTyp_nC: 4.1; Vgs_V: 16V; IdsMax_A: 1.4A; SizeAreaWB_mm2: 14; SizeArea_mm2: 7.5; SizeX_mm: 2.5; SizeY_mm: 3; SizeZ_mm: 1.1; AEC Category: Q101
Q21-Q23 Q25-Q27 = CMP-0000966-3: MOSFET, N-CH, 100 V, 200 A, KTT0002A (TO-263-2); Manufacturer: Texas Instruments; Alternate Manufacturer: None; ChType: N; Value: 100V; Value2: 118 nC; QgTyp_nC: 118; Vgs_V: 20V; IdsMax_A: 200A; SizeAreaWB_mm2: 198.208; SizeArea_mm2: 145.288; SizeX_mm: 14.3; SizeY_mm: 10.16; SizeZ_mm: 4.7; AEC Category: Q101
Q24 = CMP-0000049-3: MOSFET, P-CH, -80 V, -2.1 A, SSOT-6; Manufacturer: Fairchild Semiconductor; Alternate Manufacturer: None; ChType: P; Value: -80V; Value1: 0.23; Rdson45_ohm: 0.233; Value2: 14 nC; QgTyp_nC: 14; Vgs_V: -20V; IdsMax_A: -2.1A; SizeAreaWB_mm2: 14.82; SizeArea_mm2: 8.12; SizeX_mm: 2.8; SizeY_mm: 2.9; SizeZ_mm: 1.1; AEC Category: Q101; AEC Qualified: N; ChMode: Enhancement
Q28 = CMP-0000035-3: MOSFET, P-CH, -20 V, -0.82 A, SOT-323; Manufacturer: Diodes Inc.; Alternate Manufacturer: None; ChType: P; Value: -20V; Value1: 0.7; Rdson45_ohm: 0.75; Value2: 0.622 nC; QgTyp_nC: 0.622; Vgs_V: -6V; IdsMax_A: -820mA; SizeAreaWB_mm2: 10.24; SizeArea_mm2: 4.84; SizeX_mm: 2.2; SizeZ_mm: 1.1; AEC Category: Q101; ChMode: Enhancement
Q29 = CMP-0000776-1: MOSFET, N-CH, 60 V, 0.115 A, SOT-323; Manufacturer: Diodes Inc.; Alternate Manufacturer: None; U/M: EA; ChType: N; Value: 60V; Value1: 7; Rdson45_ohm: 7.5; Vgs_V: 20V; IdsMax_A: 115mA; SizeAreaWB_mm2: 10.24; SizeArea_mm2: 4.84; SizeX_mm: 2.2; SizeZ_mm: 1.1; AEC Category: Q101
Q30 Q31 = CMP-0000992-1: MOSFET, N-CH, 100 V, 3.3 A, SOT-223; Alternate Manufacturer: None; Manufacturer: Fairchild Semiconductor; SizeZ_mm: 1.6; ChType: N; Value2: 4.1 nC; Value1: 0.14; VdsMax_V: 100V; SizeX_mm: 6.5; SizeY_mm: 7; Vgs_V: 20V; Value: 100V; Rdson45_ohm: 0.145; SizeArea_mm2: 45.5; AEC Category: Q101; IdsMax_A: 3.3A; SizeAreaWB_mm2: 76.5; U/M: EA; QgTyp_nC: 4.1
R123 = CMP-0022201-5: RES, 200, 1%, 0.1 W, AEC-Q200 Grade 0, 0603; Manufacturer: Vishay-Dale; Value: 200; Value_Code: 200R; Power_W: 100mW; Value2: 0.1W; VDC_V: 75V; TempCo: 100 ppm/C; SizeArea_mm2: 1.28; SizeX_mm: 1.6; SizeY_mm: 0.8; SizeZ_mm: 1; EIA_Code: E96; AEC Category: Q200; AEC Qualified: Y; AEC Grade: 0
R124 = CMP-0017628-3: RES, 499, 1%, 0.25 W, AEC-Q200 Grade 0, 1206; Manufacturer: Panasonic; Value: 499; Value_Code: 499R; Power_W: 250mW; Value2: 0.25W; VDC_V: 200V; TempCo: 100 ppm/C; SizeArea_mm2: 5.12; SizeX_mm: 3.2; SizeY_mm: 1.6; SizeZ_mm: 1.35; EIA_Code: E96; AEC Category: Q200; AEC Qualified: Y; AEC Grade: 0; SizeAreaWB_mm2: 10.92
R125 R132 R138 = CMP-0025702-4: RES, 10 M, 5%, 0.1 W, AEC-Q200 Grade 0, 0603; Manufacturer: Vishay-Dale; Value: 10Meg; Value_Code: 10M0; Power_W: 100mW; Value2: 0.1W; VDC_V: 75V; TempCo: 200 ppm/C; SizeArea_mm2: 1.28; SizeX_mm: 1.6; SizeY_mm: 0.8; SizeZ_mm: 1; EIA_Code: E24; AEC Category: Q200; AEC Qualified: Y; AEC Grade: 0
R126 R139 R141 = CMP-0024283-3: RES, 49.9 k, 0.1%, 0.1 W, 0603; Manufacturer: Yageo America; Value: 49.9k; Value_Code: 49k9; Power_W: 100mW; Value2: 0.1W; VDC_V: 75V; TempCo: 25 ppm/C; SizeArea_mm2: 1.28; SizeX_mm: 1.6; SizeY_mm: 0.8; SizeZ_mm: 1; EIA_Code: E192; U/M: EA; AEC Category: Q200
R127 = CMP-0025736-4: RES, 1.0 M, 5%, 0.1 W, AEC-Q200 Grade 0, 0603; Manufacturer: Vishay-Dale; Value: 1.0Meg; Res_ohm: 1M; Value_Code: 1M00; Power_W: 100mW; Value2: 0.1W; VDC_V: 75V; TempCo: 200 ppm/C; SizeArea_mm2: 1.28; SizeX_mm: 1.6; SizeY_mm: 0.8; SizeZ_mm: 1; EIA_Code: E24; AEC Category: Q200; AEC Qualified: Y; AEC Grade: 0
R128 R129 = CRCW2512604RFKEG: RES SMD 510 OHM 5% 1W 2512; Manufacturer: Yageo; CompType: Resistor; Value: 510; Value_Code: 510R; Tolerance_%: 1; VDC_V: 500; TempCo: 100 ppm/C; SizeArea_mm2: 20.16; SizeX_mm: 6.3; SizeY_mm: 3.2; SizeZ_mm: 0.71; EIA_Code: E96; U/M: EA; AEC Category: Q200; AEC Qualified: Y; AEC Grade: 0
R130 = CRCW080556K0JNEA: RES, 56 k, 5%, 0.125 W, 0805; Manufacturer: Yageo; CompType: Resistor; Value: 56k; Res_ohm: 56000; Value_Code: 56k0; Tolerance_%: 5; Power_W: 0.125; Value2: 0.125W; VDC_V: 150; TempCo: 200 ppm/C; SizeArea_mm2: 2.5; SizeX_mm: 2; SizeY_mm: 1.25; SizeZ_mm: 1.45; EIA_Code: E24; U/M: EA; AEC Category: Q200
R131 = CMP-0021991-4: as R100-R102 on sheet MCU and Communication
R133-R135 = CMP-0021317-3: RES, 511, 1%, 0.125 W, AEC-Q200 Grade 0, 0805; Manufacturer: Vishay-Dale; Value: 511; Value_Code: 511R; Power_W: 125mW; Value2: 0.125W; VDC_V: 150V; TempCo: 100 ppm/C; SizeArea_mm2: 2.5; SizeX_mm: 2; SizeY_mm: 1.25; SizeZ_mm: 1.45; EIA_Code: E96; AEC Category: Q200; AEC Qualified: Y; AEC Grade: 0
R136 = CMP-0022481-5: RES, 511, 1%, 0.1 W, AEC-Q200 Grade 0, 0603; Manufacturer: Vishay-Dale; Value: 511; Value_Code: 511R; Power_W: 100mW; Value2: 0.1W; VDC_V: 75V; TempCo: 100 ppm/C; SizeArea_mm2: 1.28; SizeX_mm: 1.6; SizeY_mm: 0.8; SizeZ_mm: 1; EIA_Code: E96; AEC Category: Q200; AEC Qualified: Y; AEC Grade: 0
R137 R173-R175 = CMP-0025701-4: as R103 on sheet MCU and Communication
R140 = CMP-0025830-4: RES, 5.1 k, 5%, 0.1 W, AEC-Q200 Grade 0, 0603; Manufacturer: Vishay-Dale; Value: 5.1k; Value_Code: 5k10; Power_W: 100mW; Value2: 0.1W; VDC_V: 75V; TempCo: 200 ppm/C; SizeArea_mm2: 1.28; SizeX_mm: 1.6; SizeY_mm: 0.8; SizeZ_mm: 1; EIA_Code: E24; AEC Category: Q200; AEC Qualified: Y; AEC Grade: 0
R142 R143 = CMP-0025753-4: RES, 20 k, 5%, 0.1 W, AEC-Q200 Grade 0, 0603; Manufacturer: Vishay-Dale; Value: 20k; Value_Code: 20k0; Power_W: 100mW; Value2: 0.1W; VDC_V: 75V; TempCo: 200 ppm/C; SizeArea_mm2: 1.28; SizeX_mm: 1.6; SizeY_mm: 0.8; SizeZ_mm: 1; EIA_Code: E24; AEC Category: Q200; AEC Qualified: Y; AEC Grade: 0
R144-R159 = CMP-0078193-1: RES, 1.0 k, 5%, 0.1 W, AEC-Q200 Grade 0, 0402; Manufacturer: Panasonic; Value_Code: 1k00; SizeArea_mm2: 0.5; AEC Qualified: Y; AEC Category: Q200; Res_ohm: 1k; Value: 1.0k; SizeZ_mm: 0.6; Green_REACh: Passed; EIA_Code: E24; TempCo: 200 ppm/C; AEC Grade: 0; Power_W: 100mW; VDC_V: 50V; Value2: 0.1W; Green_Lifecycle: Active; U/M: EA; SizeX_mm: 1
R160 = CMP-0025781-4: RES, 300, 5%, 0.1 W, AEC-Q200 Grade 0, 0603; Manufacturer: Vishay-Dale; Power_W: 100mW; TempCo: 200 ppm/C; Value_Code: 300R; Value: 300; EIA_Code: E24; SizeX_mm: 1.6; SizeY_mm: 0.8; SizeZ_mm: 1; Value2: 0.1W; SizeArea_mm2: 1.28; AEC Qualified: Y; VDC_V: 75V; AEC Category: Q200; AEC Grade: 0
R161 R162 R178 R180 = CMP-0025700-4: RES, 100, 5%, 0.1 W, AEC-Q200 Grade 0, 0603; Manufacturer: Vishay-Dale; Power_W: 100mW; TempCo: 200 ppm/C; Value_Code: 100R; Value: 100; EIA_Code: E24; SizeX_mm: 1.6; SizeY_mm: 0.8; SizeZ_mm: 1; Value2: 0.1W; SizeArea_mm2: 1.28; AEC Qualified: Y; VDC_V: 75V; AEC Category: Q200; AEC Grade: 0
R163 R164 = CMP-0016578-1: RES, 10.0 k, 1%, 0.5 W, 1206; Manufacturer: Vishay-Dale; Power_W: 500mW; TempCo: 100 ppm/C; Value_Code: 10k0; U/M: EA; Value: 10.0k; EIA_Code: E96; Res_ohm: 10k; SizeX_mm: 3.2; SizeY_mm: 1.6; SizeZ_mm: 1.35; Value2: 0.5W; SizeArea_mm2: 5.12; AEC Category: Q200
RT6 = CMP-0002341-2: Thermistor NTC, 10.0k ohm, 1%, Disc, 5x8.4 mm; Manufacturer: SEMITEC Corporation; TaMax_C: 110°C; TaMin_C: -50°C; Power_W: 10mW; U/M: EA
U6 = CMP-0088789-1: Voltage and Temperature Protection for 3-Series to 16-Series Cell Li-Ion Batteries with Internal Delay Timer; Manufacturer: Texas Instruments; Min Supply Voltage: 5V; Standoff Height: 0.05mm; TaMin_C: -40°C; SizeZ_mm: 1.2mm; Number Of Cells: 16; Max Supply Voltage: 85V; TJmax_C: +150°C; AEC Qualified: No; TaMax_C: +110°C; Number Of Outputs: 1; Nominal Supply Current: 1uA

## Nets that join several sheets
GND: High level sch (R111.1), Monitor and Cell balancing (31 pins), Aux power (19 pins), MCU and Communication (25 pins), High-side MOSFETs and driver (15 pins)
3V3: Aux power (R172.1), MCU and Communication (11 pins)
5V: High level sch (D27.1), Aux power (R122.1), MCU and Communication (6 pins)
5V_AFE: High level sch (D27.2), Monitor and Cell balancing (C30.1 U1.34)
ALERT: Monitor and Cell balancing (U1.25), MCU and Communication (U3.26)
BAT+: High level sch (R176.1), High-side MOSFETs and driver (C59.1 D30.1 F1.3 F2.2)
BAT-: High level sch (6 pins), Monitor and Cell balancing (D1.2 Q1.2 R17.1 R88.1), Aux power (R166.1), High-side MOSFETs and driver (C58.2 C80.2 D30.2)
BAT_ADC: Monitor and Cell balancing (R85.2 R86.1), MCU and Communication (C37.2 U3.25)
BATS_EN: Monitor and Cell balancing (Q18.1), MCU and Communication (U3.13)
CANH: High level sch (P4.1), MCU and Communication (D24.1 R106.1 U4.7)
CANL: High level sch (P4.2), MCU and Communication (D24.2 R105.2 U4.6)
Cell1: High level sch (P3.2), Monitor and Cell balancing (5 pins), High-side MOSFETs and driver (R144.1)
Cell2: High level sch (P3.3), Monitor and Cell balancing (5 pins), High-side MOSFETs and driver (R145.1)
Cell3: High level sch (P3.4), Monitor and Cell balancing (5 pins), High-side MOSFETs and driver (R146.1)
Cell4: High level sch (P3.5), Monitor and Cell balancing (5 pins), High-side MOSFETs and driver (R147.1)
Cell5: High level sch (P3.6), Monitor and Cell balancing (5 pins), High-side MOSFETs and driver (R148.1)
Cell6: High level sch (P3.7), Monitor and Cell balancing (5 pins), High-side MOSFETs and driver (R149.1)
Cell7: High level sch (P3.8), Monitor and Cell balancing (5 pins), High-side MOSFETs and driver (R150.1)
Cell8: High level sch (P3.9), Monitor and Cell balancing (5 pins), High-side MOSFETs and driver (R151.1)
Cell9: High level sch (P3.10), Monitor and Cell balancing (5 pins), High-side MOSFETs and driver (R152.1)
Cell10: High level sch (P3.11), Monitor and Cell balancing (6 pins), High-side MOSFETs and driver (R153.1)
Cell11: High level sch (P3.12), Monitor and Cell balancing (5 pins), High-side MOSFETs and driver (R154.1)
Cell12: High level sch (P3.13), Monitor and Cell balancing (6 pins), High-side MOSFETs and driver (R155.1)
Cell13: High level sch (P3.14), Monitor and Cell balancing (6 pins), High-side MOSFETs and driver (R156.1)
Cell14: High level sch (P3.15), Monitor and Cell balancing (6 pins), High-side MOSFETs and driver (R157.1)
Cell15: High level sch (P3.16), Monitor and Cell balancing (6 pins), High-side MOSFETs and driver (R158.1)
Cell16: High level sch (P3.17 R176.2), Monitor and Cell balancing (8 pins), Aux power (D29.2 Q32.2 R167.1), High-side MOSFETs and driver (R159.1 R160.2)
CHG: Monitor and Cell balancing (U1.45), High-side MOSFETs and driver (R124.1)
DCHG: Monitor and Cell balancing (U1.31), MCU and Communication (U3.28)
DDSG: Monitor and Cell balancing (U1.32), MCU and Communication (U3.29)
DSG: Monitor and Cell balancing (U1.43), High-side MOSFETs and driver (D34.1 R131.1)
FETOFF: Monitor and Cell balancing (C24.1 R91.2 U1.30), MCU and Communication (U3.27), High-side MOSFETs and driver (D47.1 D48.1 D49.1)
Fuse: High level sch (D28.1 R114.2), High-side MOSFETs and driver (Q20.1 R173.1)
FUSE_AFE: High level sch (R114.1), Monitor and Cell balancing (U1.38)
FUSE_MCU: High level sch (D28.2), MCU and Communication (U3.43)
LD: Monitor and Cell balancing (U1.41), High-side MOSFETs and driver (D39.1 D42.2 R139.1)
PACK: Monitor and Cell balancing (U1.42), High-side MOSFETs and driver (D41.1 R140.1)
PACK-: High level sch (R112.2 R113.2), Monitor and Cell balancing (R87.1), Aux power (R165.1), High-side MOSFETs and driver (5 pins)
PDSG: Monitor and Cell balancing (U1.39), High-side MOSFETs and driver (D32.1 R126.1)
POW_EN: Aux power (5 pins), MCU and Communication (U3.12)
SCL_MCU: Monitor and Cell balancing (R89.1), Aux power (U7.13), MCU and Communication (P2.1 R104.2)
SDA_MCU: Monitor and Cell balancing (R90.1), Aux power (U7.14), MCU and Communication (P2.3 R103.2)
SHUT: Monitor and Cell balancing (C25.1 R92.2 U1.33), MCU and Communication (U3.30)

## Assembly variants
001: not fitted R34 R35 R46 R47 R48 R49 R50 R64 R66 R67 R72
